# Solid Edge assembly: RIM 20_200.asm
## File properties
Title: Zylinder
Author: ahadarics
Template: iso metric assembly.asm
Last saved by: ahadarics
Revision: 15
Application: Solid Edge
Username: ahadarics
Dokumentum tartalom típus: 1
Document Number: RIM 20/200
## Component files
Kit_2.par
Profilrohr.par
Kolbenstange.par
Kit_1.par
Mutter_1.par
Mutter_2.par
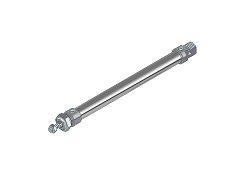
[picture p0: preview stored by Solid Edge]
